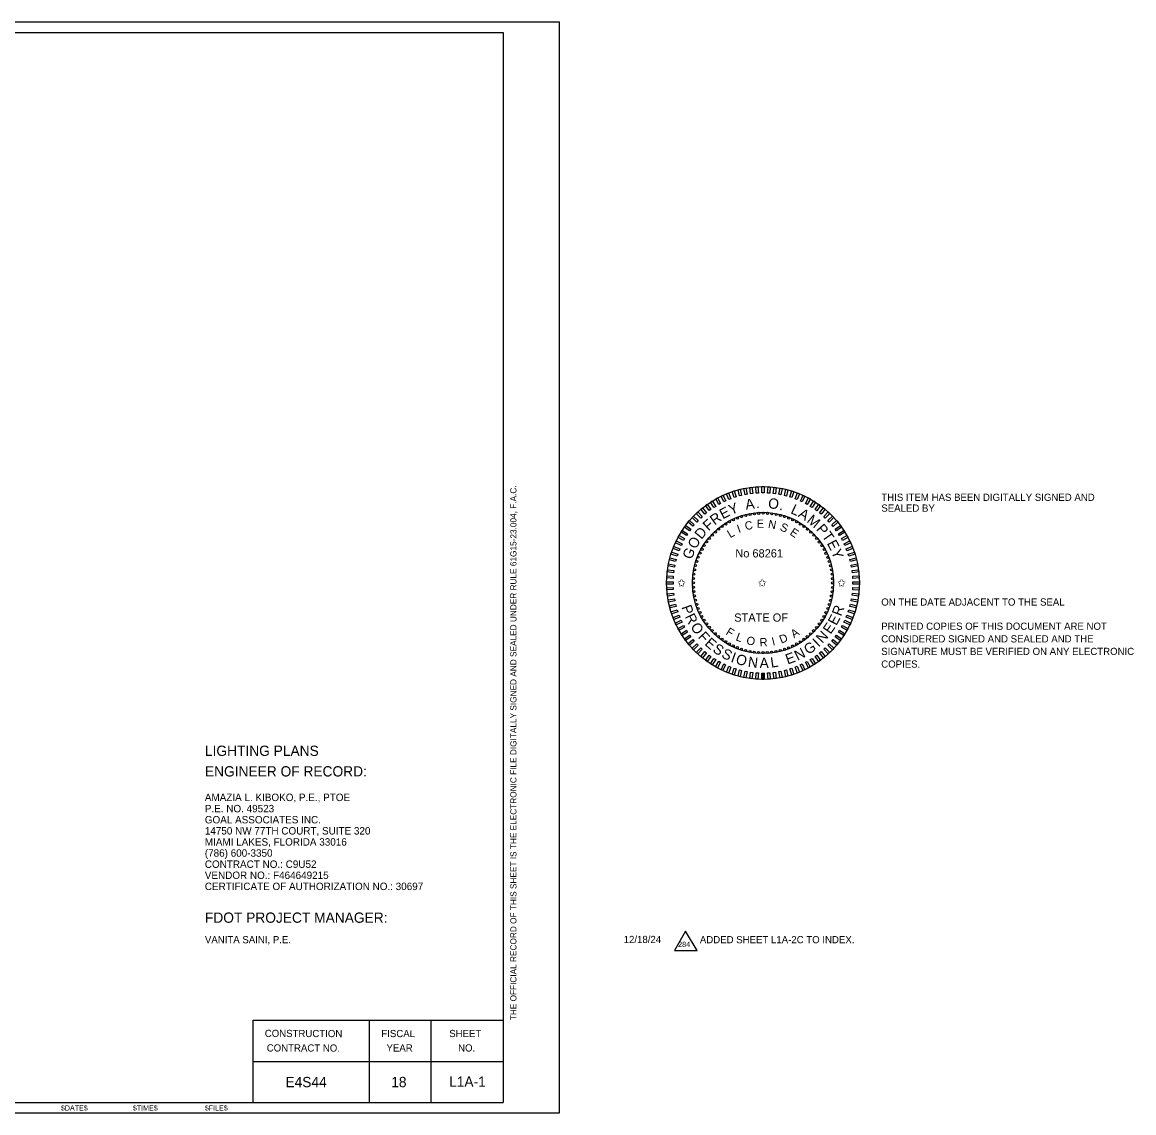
# Model space of a CAD drawing. Extents: x -827.9 to -798.1, y -2199.1 to -2182.2.
# Drawn here: x -808.95 to -798.14, y -2199.12 to -2188.52 of the extents above; entities that cross this region are included whole.
import ezdxf

# ---------------------------------------------------------------- set-up
doc = ezdxf.new("R2010")
doc.units = 0
for name, color, linetype in [('Cloud_dp', 7, 'Continuous'), ('Logo_dp', 7, 'Continuous'), ('NonPlottingEle_dp', 7, 'Continuous'), ('PlotBorder_dp', 7, 'Continuous'), ('SheetBorder_dp', 7, 'Continuous'), ('SheetLines_dp', 7, 'Continuous'), ('TextLabel', 7, 'Continuous'), ('TextMinor', 7, 'Continuous'), ('TextMisc', 7, 'Continuous'), ('TextNotes', 7, 'Continuous')]:
    doc.layers.add(name, color=color, linetype=linetype)

msp = doc.modelspace()

# ---------------------------------------------------------------- linework, layer by layer
at = {"layer": 'Cloud_dp'}
msp.add_lwpolyline([(-802.502, -2197.359), (-802.61, -2197.547), (-802.389, -2197.547)], close=True, dxfattribs=at)
at = {"layer": 'Logo_dp'}
for p, q in [((-801.759, -2194.911), (-801.759, -2194.849)), ((-801.749, -2194.911), (-801.749, -2194.849)), ((-801.739, -2194.911), (-801.739, -2194.848))]:
    msp.add_line(p, q, dxfattribs=at)
for points in [[(-801.849, -2193.104), (-801.869, -2193.107), (-801.876, -2193.045), (-801.856, -2193.042)], [(-801.794, -2193.1), (-801.814, -2193.101), (-801.818, -2193.039), (-801.798, -2193.037)], [(-801.739, -2193.098), (-801.759, -2193.098), (-801.759, -2193.036), (-801.739, -2193.036)], [(-801.684, -2193.101), (-801.704, -2193.1), (-801.7, -2193.037), (-801.68, -2193.039)], [(-801.629, -2193.107), (-801.649, -2193.104), (-801.641, -2193.042), (-801.621, -2193.045)], [(-802.162, -2193.202), (-802.179, -2193.212), (-802.209, -2193.157), (-802.192, -2193.147)], [(-802.112, -2193.177), (-802.131, -2193.186), (-802.157, -2193.13), (-802.139, -2193.121)], [(-802.062, -2193.156), (-802.08, -2193.164), (-802.103, -2193.106), (-802.085, -2193.098)], [(-802.01, -2193.138), (-802.029, -2193.144), (-802.048, -2193.085), (-802.029, -2193.079)], [(-801.957, -2193.123), (-801.976, -2193.128), (-801.992, -2193.068), (-801.972, -2193.063)], [(-801.903, -2193.112), (-801.923, -2193.116), (-801.934, -2193.055), (-801.915, -2193.051)], [(-801.575, -2193.116), (-801.595, -2193.112), (-801.583, -2193.051), (-801.563, -2193.055)], [(-801.522, -2193.129), (-801.541, -2193.124), (-801.526, -2193.063), (-801.506, -2193.068)], [(-801.469, -2193.144), (-801.488, -2193.138), (-801.469, -2193.079), (-801.45, -2193.085)], [(-801.417, -2193.164), (-801.436, -2193.156), (-801.413, -2193.098), (-801.394, -2193.106)], [(-801.367, -2193.186), (-801.385, -2193.178), (-801.359, -2193.121), (-801.341, -2193.13)], [(-801.319, -2193.212), (-801.336, -2193.202), (-801.306, -2193.147), (-801.288, -2193.157)], [(-802.299, -2193.293), (-802.314, -2193.306), (-802.354, -2193.258), (-802.339, -2193.245)], [(-802.255, -2193.26), (-802.271, -2193.271), (-802.308, -2193.221), (-802.292, -2193.209)], [(-802.209, -2193.229), (-802.226, -2193.24), (-802.26, -2193.187), (-802.243, -2193.177)], [(-801.272, -2193.24), (-801.289, -2193.229), (-801.255, -2193.177), (-801.238, -2193.187)], [(-801.226, -2193.272), (-801.243, -2193.26), (-801.206, -2193.209), (-801.19, -2193.221)], [(-801.183, -2193.306), (-801.199, -2193.293), (-801.159, -2193.245), (-801.144, -2193.258)], [(-802.417, -2193.408), (-802.43, -2193.423), (-802.478, -2193.384), (-802.465, -2193.368)], [(-802.38, -2193.367), (-802.394, -2193.382), (-802.439, -2193.339), (-802.425, -2193.324)], [(-802.341, -2193.329), (-802.355, -2193.343), (-802.398, -2193.297), (-802.383, -2193.283)], [(-801.143, -2193.343), (-801.157, -2193.329), (-801.115, -2193.283), (-801.1, -2193.297)], [(-801.104, -2193.382), (-801.118, -2193.367), (-801.072, -2193.324), (-801.059, -2193.339)], [(-801.068, -2193.424), (-801.081, -2193.408), (-801.033, -2193.368), (-801.02, -2193.384)], [(-802.482, -2193.496), (-802.493, -2193.513), (-802.546, -2193.48), (-802.535, -2193.463)], [(-802.451, -2193.451), (-802.463, -2193.467), (-802.513, -2193.431), (-802.501, -2193.414)], [(-801.035, -2193.467), (-801.047, -2193.451), (-800.996, -2193.414), (-800.985, -2193.431)], [(-801.005, -2193.513), (-801.016, -2193.496), (-800.963, -2193.463), (-800.952, -2193.48)], [(-802.536, -2193.592), (-802.545, -2193.61), (-802.601, -2193.583), (-802.593, -2193.565)], [(-802.511, -2193.543), (-802.521, -2193.561), (-802.575, -2193.531), (-802.566, -2193.513)], [(-800.977, -2193.561), (-800.987, -2193.543), (-800.932, -2193.513), (-800.923, -2193.531)], [(-800.953, -2193.61), (-800.961, -2193.592), (-800.905, -2193.565), (-800.896, -2193.584)], [(-802.578, -2193.693), (-802.584, -2193.713), (-802.644, -2193.693), (-802.637, -2193.674)], [(-802.559, -2193.642), (-802.566, -2193.661), (-802.624, -2193.638), (-802.617, -2193.619)], [(-800.932, -2193.661), (-800.939, -2193.642), (-800.881, -2193.619), (-800.874, -2193.638)], [(-800.914, -2193.713), (-800.92, -2193.694), (-800.86, -2193.674), (-800.854, -2193.694)], [(-802.607, -2193.8), (-802.61, -2193.819), (-802.672, -2193.808), (-802.668, -2193.788)], [(-802.594, -2193.746), (-802.599, -2193.766), (-802.659, -2193.75), (-802.654, -2193.731)], [(-800.899, -2193.766), (-800.904, -2193.746), (-800.843, -2193.731), (-800.838, -2193.75)], [(-800.888, -2193.82), (-800.891, -2193.8), (-800.83, -2193.788), (-800.826, -2193.808)], [(-802.622, -2193.908), (-802.623, -2193.929), (-802.685, -2193.925), (-802.684, -2193.904)], [(-802.616, -2193.854), (-802.618, -2193.874), (-802.68, -2193.866), (-802.678, -2193.846)], [(-800.88, -2193.874), (-800.882, -2193.854), (-800.82, -2193.846), (-800.818, -2193.866)], [(-800.875, -2193.929), (-800.876, -2193.909), (-800.814, -2193.905), (-800.813, -2193.925)], [(-802.624, -2193.963), (-802.624, -2193.984), (-802.686, -2193.984), (-802.686, -2193.963)], [(-802.623, -2194.018), (-802.622, -2194.038), (-802.684, -2194.042), (-802.685, -2194.022)], [(-800.876, -2194.039), (-800.875, -2194.018), (-800.813, -2194.022), (-800.814, -2194.043)], [(-800.874, -2193.984), (-800.874, -2193.964), (-800.812, -2193.964), (-800.812, -2193.984)], [(-802.618, -2194.073), (-802.616, -2194.093), (-802.678, -2194.101), (-802.68, -2194.081)], [(-802.61, -2194.127), (-802.607, -2194.147), (-802.668, -2194.159), (-802.672, -2194.139)], [(-800.891, -2194.147), (-800.888, -2194.128), (-800.826, -2194.139), (-800.83, -2194.159)], [(-800.882, -2194.093), (-800.88, -2194.073), (-800.818, -2194.081), (-800.82, -2194.101)], [(-802.599, -2194.181), (-802.594, -2194.201), (-802.655, -2194.216), (-802.66, -2194.197)], [(-802.584, -2194.234), (-802.578, -2194.253), (-802.637, -2194.273), (-802.644, -2194.254)], [(-800.92, -2194.254), (-800.914, -2194.234), (-800.854, -2194.254), (-800.861, -2194.273)], [(-800.904, -2194.201), (-800.899, -2194.181), (-800.838, -2194.197), (-800.844, -2194.217)], [(-802.566, -2194.286), (-802.559, -2194.305), (-802.617, -2194.328), (-802.624, -2194.309)], [(-802.545, -2194.337), (-802.536, -2194.355), (-802.593, -2194.382), (-802.602, -2194.363)], [(-800.962, -2194.355), (-800.953, -2194.337), (-800.896, -2194.364), (-800.905, -2194.382)], [(-800.939, -2194.305), (-800.932, -2194.286), (-800.874, -2194.309), (-800.881, -2194.328)], [(-802.521, -2194.386), (-802.511, -2194.404), (-802.566, -2194.434), (-802.575, -2194.416)], [(-802.493, -2194.434), (-802.482, -2194.451), (-802.535, -2194.484), (-802.546, -2194.467)], [(-801.016, -2194.451), (-801.005, -2194.434), (-800.952, -2194.467), (-800.963, -2194.484)], [(-800.987, -2194.404), (-800.977, -2194.386), (-800.923, -2194.416), (-800.932, -2194.434)], [(-802.463, -2194.48), (-802.451, -2194.496), (-802.502, -2194.533), (-802.513, -2194.516)], [(-802.43, -2194.523), (-802.417, -2194.539), (-802.465, -2194.579), (-802.478, -2194.563)], [(-801.081, -2194.539), (-801.068, -2194.524), (-801.02, -2194.563), (-801.033, -2194.579)], [(-801.047, -2194.496), (-801.035, -2194.48), (-800.985, -2194.516), (-800.997, -2194.533)], [(-802.394, -2194.565), (-802.38, -2194.58), (-802.426, -2194.623), (-802.439, -2194.608)], [(-802.355, -2194.604), (-802.341, -2194.618), (-802.383, -2194.664), (-802.398, -2194.65)], [(-802.315, -2194.641), (-802.299, -2194.654), (-802.339, -2194.702), (-802.354, -2194.689)], [(-801.199, -2194.654), (-801.184, -2194.641), (-801.144, -2194.689), (-801.159, -2194.702)], [(-801.157, -2194.618), (-801.143, -2194.605), (-801.1, -2194.65), (-801.115, -2194.664)], [(-801.118, -2194.58), (-801.104, -2194.565), (-801.059, -2194.608), (-801.073, -2194.623)], [(-802.272, -2194.675), (-802.255, -2194.687), (-802.292, -2194.738), (-802.308, -2194.726)], [(-802.226, -2194.707), (-802.209, -2194.718), (-802.243, -2194.77), (-802.26, -2194.76)], [(-802.179, -2194.735), (-802.162, -2194.745), (-802.192, -2194.8), (-802.21, -2194.79)], [(-802.131, -2194.761), (-802.113, -2194.77), (-802.139, -2194.826), (-802.157, -2194.817)], [(-801.386, -2194.77), (-801.367, -2194.761), (-801.341, -2194.818), (-801.359, -2194.826)], [(-801.336, -2194.745), (-801.319, -2194.736), (-801.289, -2194.79), (-801.306, -2194.8)], [(-801.289, -2194.718), (-801.272, -2194.707), (-801.238, -2194.76), (-801.255, -2194.771)], [(-801.243, -2194.687), (-801.227, -2194.676), (-801.19, -2194.726), (-801.206, -2194.738)], [(-802.081, -2194.783), (-802.062, -2194.791), (-802.085, -2194.849), (-802.104, -2194.841)], [(-802.029, -2194.803), (-802.01, -2194.809), (-802.029, -2194.868), (-802.048, -2194.862)], [(-801.976, -2194.819), (-801.957, -2194.824), (-801.972, -2194.884), (-801.992, -2194.879)], [(-801.923, -2194.831), (-801.903, -2194.835), (-801.915, -2194.896), (-801.935, -2194.892)], [(-801.869, -2194.84), (-801.849, -2194.843), (-801.857, -2194.905), (-801.877, -2194.902)], [(-801.814, -2194.846), (-801.794, -2194.847), (-801.798, -2194.91), (-801.818, -2194.909)], [(-801.759, -2194.849), (-801.739, -2194.849), (-801.739, -2194.911), (-801.759, -2194.911)], [(-801.704, -2194.847), (-801.684, -2194.846), (-801.68, -2194.909), (-801.7, -2194.91)], [(-801.649, -2194.843), (-801.629, -2194.84), (-801.622, -2194.902), (-801.642, -2194.905)], [(-801.595, -2194.835), (-801.575, -2194.831), (-801.563, -2194.893), (-801.583, -2194.896)], [(-801.541, -2194.824), (-801.522, -2194.819), (-801.506, -2194.879), (-801.526, -2194.884)], [(-801.488, -2194.809), (-801.469, -2194.803), (-801.45, -2194.862), (-801.469, -2194.868)], [(-801.436, -2194.791), (-801.418, -2194.783), (-801.395, -2194.841), (-801.413, -2194.849)]]:
    msp.add_lwpolyline(points, close=True, dxfattribs=at)
for centre in [(-802.075, -2193.38), (-802.037, -2193.36), (-801.998, -2193.343), (-801.958, -2193.329), (-801.917, -2193.317), (-801.875, -2193.308), (-801.833, -2193.301), (-801.791, -2193.297), (-801.748, -2193.296), (-801.706, -2193.297), (-801.664, -2193.301), (-801.621, -2193.308), (-801.58, -2193.317), (-801.539, -2193.329), (-801.499, -2193.344), (-801.46, -2193.361), (-801.422, -2193.38), (-802.212, -2193.479), (-802.18, -2193.451), (-802.147, -2193.425), (-802.112, -2193.401), (-801.386, -2193.402), (-801.35, -2193.426), (-801.317, -2193.452), (-801.285, -2193.48), (-802.297, -2193.575), (-802.271, -2193.541), (-802.242, -2193.509), (-801.255, -2193.51), (-801.227, -2193.542), (-801.201, -2193.576), (-802.362, -2193.685), (-802.342, -2193.647), (-802.321, -2193.61), (-801.177, -2193.611), (-801.155, -2193.648), (-801.136, -2193.686), (-802.405, -2193.805), (-802.393, -2193.764), (-802.379, -2193.724), (-801.119, -2193.725), (-801.105, -2193.765), (-801.093, -2193.806), (-802.421, -2193.888), (-802.414, -2193.846), (-801.083, -2193.847), (-801.077, -2193.889), (-802.426, -2193.973), (-802.425, -2193.93), (-802.425, -2194.016), (-801.073, -2193.932), (-801.073, -2194.017), (-801.072, -2193.974), (-802.421, -2194.058), (-802.415, -2194.1), (-801.084, -2194.101), (-801.077, -2194.059), (-802.405, -2194.141), (-802.393, -2194.182), (-802.379, -2194.222), (-801.119, -2194.223), (-801.105, -2194.183), (-801.093, -2194.143), (-802.362, -2194.261), (-802.343, -2194.299), (-802.321, -2194.336), (-801.177, -2194.337), (-801.156, -2194.3), (-801.136, -2194.262), (-802.297, -2194.371), (-802.271, -2194.405), (-802.243, -2194.437), (-801.256, -2194.438), (-801.227, -2194.406), (-801.201, -2194.372), (-802.213, -2194.467), (-802.181, -2194.495), (-802.148, -2194.521), (-802.112, -2194.545), (-802.076, -2194.567), (-801.423, -2194.567), (-801.386, -2194.546), (-801.351, -2194.522), (-801.318, -2194.496), (-801.286, -2194.468), (-802.038, -2194.586), (-801.999, -2194.603), (-801.959, -2194.618), (-801.918, -2194.63), (-801.876, -2194.639), (-801.834, -2194.646), (-801.792, -2194.65), (-801.749, -2194.651), (-801.707, -2194.65), (-801.665, -2194.646), (-801.623, -2194.639), (-801.581, -2194.63), (-801.54, -2194.618), (-801.5, -2194.604), (-801.461, -2194.587)]:
    msp.add_circle(centre, 0.01, dxfattribs=at)
at = {"layer": 'NonPlottingEle_dp'}
for radius in [0.937, 0.687]:
    msp.add_circle((-801.749, -2193.974), radius, dxfattribs=at)
at = {"layer": 'PlotBorder_dp'}
msp.add_lwpolyline([(-820.227, -2199.124), (-803.727, -2199.124), (-803.727, -2188.524), (-820.227, -2188.524)], close=True, dxfattribs=at)
at = {"layer": 'SheetBorder_dp'}
for p, q in [((-819.677, -2188.624), (-804.277, -2188.624)), ((-804.277, -2188.624), (-804.277, -2199.024)), ((-819.677, -2199.024), (-804.277, -2199.024))]:
    msp.add_line(p, q, dxfattribs=at)
at = {"layer": 'SheetLines_dp'}
for p, q in [((-806.708, -2198.224), (-804.277, -2198.224)), ((-806.708, -2199.024), (-806.708, -2198.224)), ((-805.577, -2199.024), (-805.577, -2198.224)), ((-804.977, -2199.024), (-804.977, -2198.224)), ((-806.708, -2198.624), (-804.277, -2198.624))]:
    msp.add_line(p, q, dxfattribs=at)

# ---------------------------------------------------------------- texts
at = {"layer": 'Cloud_dp'}
msp.add_text('284', height=0.051, rotation=0, dxfattribs=at).set_placement((-802.575, -2197.512))
at = {"layer": 'Logo_dp'}
for s, height, rotation, p in [('A', 0.1, 8.8088, (-801.914, -2193.263)), ('O', 0.1, 352.1877, (-801.704, -2193.245)), ('E', 0.1, 28.1055, (-802.139, -2193.357)), ('Y', 0.1, 21.0633, (-802.061, -2193.314)), ('.', 0.1, 1.0418, (-801.816, -2193.247)), ('.', 0.1, 343.5268, (-801.595, -2193.261)), ('L', 0.1, 334.6727, (-801.487, -2193.293)), ('A', 0.1, 328.4096, (-801.414, -2193.325)), ('F', 0.1, 42.3772, (-802.279, -2193.473)), ('R', 0.1, 35.9269, (-802.22, -2193.416)), ('C', 0.08, 12.2025, (-801.917, -2193.462)), ('E', 0.08, 0.4186, (-801.809, -2193.438)), ('N', 0.08, 349.2914, (-801.704, -2193.437)), ('M', 0.1, 320.6426, (-801.33, -2193.377)), ('D', 0.1, 50.8569, (-802.347, -2193.556)), ('L', 0.08, 30.4021, (-802.068, -2193.54)), ('I', 0.08, 20.0117, (-801.985, -2193.489)), ('S', 0.08, 337.0221, (-801.591, -2193.459)), ('E', 0.08, 325.8663, (-801.495, -2193.499)), ('P', 0.1, 311.1966, (-801.237, -2193.454)), ('T', 0.1, 304.4563, (-801.18, -2193.517)), ('O', 0.1, 59.5178, (-802.403, -2193.651)), ('E', 0.1, 297.6315, (-801.13, -2193.588)), ('G', 0.1, 68.0518, (-802.444, -2193.752)), ('Y', 0.1, 290.5893, (-801.087, -2193.667)), ('P', 0.1, 289.4055, (-802.544, -2194.208)), ('R', 0.1, 69.5134, (-800.989, -2194.303)), ('R', 0.1, 296.1458, (-802.511, -2194.3)), ('E', 0.1, 62.4712, (-801.035, -2194.394)), ('O', 0.1, 303.9671, (-802.459, -2194.4)), ('F', 0.1, 312.628, (-802.387, -2194.502)), ('F', 0.08, 328.7241, (-802.117, -2194.47)), ('A', 0.08, 34.4992, (-801.447, -2194.513)), ('N', 0.1, 47.1788, (-801.171, -2194.567)), ('E', 0.1, 55.4289, (-801.092, -2194.478)), ('E', 0.1, 319.0783, (-802.323, -2194.571)), ('L', 0.08, 339.2916, (-802.02, -2194.529)), ('O', 0.08, 349.6821, (-801.915, -2194.569)), ('R', 0.08, 2.3398, (-801.781, -2194.591)), ('I', 0.08, 14.2037, (-801.653, -2194.584)), ('D', 0.08, 22.0128, (-801.571, -2194.565)), ('G', 0.1, 35.1115, (-801.308, -2194.675)), ('I', 0.1, 43.6456, (-801.209, -2194.602)), ('S', 0.1, 326.1206, (-802.246, -2194.637)), ('S', 0.1, 333.193, (-802.16, -2194.693)), ('I', 0.1, 340.2654, (-802.069, -2194.738)), ('O', 0.1, 343.7986, (-802.021, -2194.756)), ('E', 0.1, 19.8191, (-801.509, -2194.767)), ('N', 0.1, 26.8614, (-801.413, -2194.731)), ('N', 0.1, 352.4595, (-801.9, -2194.788)), ('A', 0.1, 0.7097, (-801.782, -2194.801)), ('L', 0.1, 8.4767, (-801.669, -2194.798))]:
    msp.add_text(s, height=height, rotation=rotation, dxfattribs=at).set_placement(p)
for s, p in [('No 68261', (-802.018, -2193.726)), ('✩', (-802.584, -2194.011)), ('✩', (-801.799, -2194.011)), ('✩', (-801.027, -2194.011)), ('STATE OF', (-802.029, -2194.35))]:
    msp.add_text(s, height=0.08, dxfattribs=at).set_placement(p)
at = {"layer": 'TextLabel'}
for s, height, p in [('LIGHTING PLANS', 0.1, (-807.177, -2195.655)), ('ENGINEER OF RECORD:', 0.1, (-807.177, -2195.855)), ('AMAZIA L. KIBOKO, P.E., PTOE', 0.07202, (-807.178, -2196.094)), ('P.E. NO. 49523', 0.07202, (-807.178, -2196.203)), ('GOAL ASSOCIATES INC. ', 0.07202, (-807.178, -2196.311)), ('14750 NW 77TH COURT, SUITE 320', 0.07202, (-807.178, -2196.419)), ('MIAMI LAKES, FLORIDA 33016', 0.07202, (-807.178, -2196.527)), ('(786) 600-3350', 0.07202, (-807.178, -2196.635)), ('CONTRACT NO.: C9U52', 0.07202, (-807.178, -2196.743)), ('VENDOR NO.: F464649215', 0.07202, (-807.178, -2196.851)), ('CERTIFICATE OF AUTHORIZATION NO.: 30697', 0.07202, (-807.178, -2196.959)), ('E4S44', 0.1, (-806.394, -2198.875)), ('18', 0.1, (-805.365, -2198.875)), ('L1A-1', 0.1, (-804.802, -2198.871))]:
    msp.add_text(s, height=height, dxfattribs=at).set_placement(p)
at = {"layer": 'TextMinor'}
for s, p in [('12/18/24', (-803.104, -2197.474)), ('ADDED SHEET L1A-2C TO INDEX.', (-802.363, -2197.476))]:
    msp.add_text(s, height=0.07, dxfattribs=at).set_placement(p)
for s, p in [('$DATE$', (-808.578, -2199.102)), ('$TIME$', (-807.878, -2199.102)), ('$FILE$', (-807.178, -2199.102))]:
    msp.add_text(s, height=0.05, rotation=360, dxfattribs=at).set_placement(p)
at = {"layer": 'TextMisc'}
msp.add_text('THE OFFICIAL RECORD OF THIS SHEET IS THE ELECTRONIC FILE DIGITALLY SIGNED AND SEALED UNDER RULE 61G15-23.004, F.A.C.', height=0.06, rotation=90, dxfattribs=at).set_placement((-804.147, -2198.224))
for s, p in [('THIS ITEM HAS BEEN DIGITALLY SIGNED AND ', (-800.598, -2193.176)), ('SEALED BY', (-800.598, -2193.281)), ('ON THE DATE ADJACENT TO THE SEAL', (-800.599, -2194.194)), ('PRINTED COPIES OF THIS DOCUMENT ARE NOT ', (-800.599, -2194.429)), ('CONSIDERED SIGNED AND SEALED AND THE ', (-800.599, -2194.552)), ('SIGNATURE MUST BE VERIFIED ON ANY ELECTRONIC ', (-800.599, -2194.674)), ('COPIES.', (-800.599, -2194.797))]:
    msp.add_text(s, height=0.07, dxfattribs=at).set_placement(p)
at = {"layer": 'TextNotes'}
for s, height, p in [('FDOT PROJECT MANAGER:', 0.1, (-807.177, -2197.277)), ('VANITA SAINI, P.E.', 0.07, (-807.177, -2197.476))]:
    msp.add_text(s, height=height, dxfattribs=at).set_placement(p)
for s, p in [('CONSTRUCTION', (-806.595, -2198.387)), ('FISCAL', (-805.461, -2198.388)), ('SHEET', (-804.801, -2198.388)), ('CONTRACT NO.', (-806.576, -2198.528)), ('YEAR', (-805.411, -2198.528)), ('NO.', (-804.715, -2198.528))]:
    msp.add_text(s, height=0.07, rotation=359.8607, dxfattribs=at).set_placement(p)

doc.saveas('drawing.dxf')
